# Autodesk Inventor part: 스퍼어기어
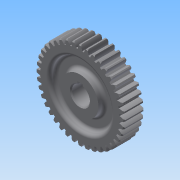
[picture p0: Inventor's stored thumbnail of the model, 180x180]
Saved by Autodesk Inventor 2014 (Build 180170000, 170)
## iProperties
Created: 2020-11
Part Number: 스퍼어기어
Material: 일반
Document SubType Name: Modeling
Designer: NET
Density: 1 g/cm^3
Appearance: 기본값
Mass: 70.096 g
Surface Area: 222.598 cm^2
Volume: 70.096 cm^3
Author: NET
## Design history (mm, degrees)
sketch "스케치1"
  geometry: L1 (-9.5, 0)-(9.5, 0); L2 (-9.5, 8.5)-(-9.5, 17.5); L3 (-9.5, 17.5)-(-3.5, 17.5); L4 (-3.5, 17.5)-(-3.5, 29); L5 (-3.5, 29)-(-9.5, 29); L6 (-9.5, 29)-(-9.5, 37.5); L7 (-9.5, 37.5)-(9.5, 37.5); L8 (9.5, 37.5)-(9.5, 29); L9 (9.5, 29)-(3.5, 29); L10 (3.5, 29)-(3.5, 17.5); L11 (3.5, 17.5)-(9.5, 17.5); L12 (9.5, 17.5)-(9.5, 8.5); L13 (9.5, 8.5)-(-9.5, 8.5); 2 further points
  constraints: 26 end point, 8 parallel, 4 vertical alignment, 2 collinear, 2 horizontal alignment, 2 perpendicular, 1 coincident, 1 horizontal, 1 midpoint
  dimensions: "d0" = 19 distance of L1.start L1.end; "d1" = 17 diameter of L13 L1; "d2" = 35 diameter of L11 L1; "d3" = 58 diameter of L9 L1; "d4" = 75 diameter of L7 L1; "d5" = 7 distance between parallel lines of L10 L4; "d6" = 6 distance from line of L2.end L4
revolve "회전1" sketch "스케치1" stored, may be unused: angle "d7" = 90 deg
sketch "스케치2"
  geometry: C1 r 29 at (0, 0) reference; A1 r 37.5 centre (0, 0) between (-2.07, 37.443) and (2.07, 37.443) reference; A2 r 40 centre (0, 0) between (1.57, 39.969) and (-1.57, 39.969); A3 r 42 centre (0, 0) between (0.57, 41.996) and (-0.57, 41.996); A4 r 9.223 centre (7.138, 36.933) between (-0.57, 41.996) and (-2.07, 37.443); A5 r 9.223 centre (-7.138, 36.933) between (2.07, 37.443) and (0.57, 41.996); 2 further points
  constraints: 14 point on circle, 4 centre point, 2 coincident, 2 vertical alignment, 1 equal radius
  dimensions: "d8" = 40 radius of A2; "d9" = 42 radius of A3; "d10" = 0.5 horizontal distance of A1.start A2.end; "d11" = 1 horizontal distance of A2.end A3.end; "d12" = 1.57 horizontal distance of point (0, 42) A2.end
extrude "돌출1" join sketch "스케치2" distance "d13" = 19; taper "d14" = 0 deg
chamfer "모따기1" distance "d15" = 1; stored, may be unused: second distance "d16" = 2, angle "d17" = 45 deg
sketch "스케치3"
  geometry: L1 (-2.5, 10.8)-(2.5, 10.8); L2 (2.5, 10.8)-(2.5, 8.124); L3 (2.5, 8.124)-(-2.5, 8.124); L4 (-2.5, 8.124)-(-2.5, 10.8); C1 r 17.5 at (0, 0) reference; 2 further points
  constraints: 8 end point, 2 parallel, 1 horizontal, 1 midpoint, 1 perpendicular, 1 vertical alignment, 2 other
  dimensions: "d22" = 19.3 dimension on L1; "d23" = 5 distance of L1.start L1.end
extrude "돌출2" cut sketch "스케치3" stored distance "d24" = 19; taper "d25" = 0 deg
fillet "모깎기1" dims "d26" = 3
chamfer "모따기2" distance "d27" = 1; stored, may be unused: second distance "d28" = 2, angle "d29" = 45 deg
node "솔리드1"
pattern_circular "원형 패턴1" dims angle "d19" = 360 deg
